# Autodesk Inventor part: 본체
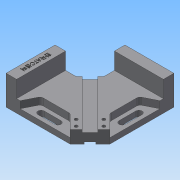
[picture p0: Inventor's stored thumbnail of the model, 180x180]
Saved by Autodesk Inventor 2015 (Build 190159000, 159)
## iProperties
Created: 2019-04
Part Number: 본체
Material: 알루미늄 6061
Document SubType Name: Modeling
Designer: user
Density: 2.7 g/cm^3
Appearance: 기본값
Author: user
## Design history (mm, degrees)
sketch "스케치1"
  geometry: L1 (60, 60)-(-60, 60); L2 (-60, 60)-(-60, -60); L3 (-60, -60)-(60, -60); L4 (60, -60)-(60, 60); L5 (60, 60)-(-60, -60); L6 (-60, 60)-(60, -60); 1 further point
  constraints: 12 end point, 2 midpoint, 2 parallel, 1 horizontal, 1 perpendicular
  dimensions: "d0" = 120 distance of L2.end L3.end; "d1" = 120 distance of L1.end L2.end
extrude "돌출1" new body sketch "스케치1" distance "d2" = 42; taper "d3" = 0 deg
sketch "스케치2"
  geometry: L1 (60, 60)-(-60, 60) reference; L2 (-60, 60)-(-60, -60) reference; L3 (60, -60)-(-45, -60); L4 (-45, -60)-(-45, 45); L5 (-45, 45)-(60, 45); L6 (60, 45)-(60, -60); 1 further point
  constraints: 8 end point, 2 parallel, 1 horizontal, 1 perpendicular
  dimensions: "d4" = 15 distance between parallel lines of L2 L4; "d5" = 15 distance between parallel lines of L1 L5
extrude "돌출2" cut sketch "스케치2" distance "d6" = 24; taper "d7" = 0 deg
sketch "스케치4"
  geometry: L1 (60, 45)-(60, -60) reference; L2 (60, -60)-(-45, -60) reference; L3 (60, -60)-(31.716, -60); L4 (60, -31.716)-(60, -60); L5 (31.716, -60)-(60, -31.716); 1 further point
  constraints: 6 end point, 2 point on line, 1 collinear
  dimensions: "d13" = 20 distance from line of L5 L1.end; "d14" = 45 deg angle of L1 L5
extrude "돌출3" cut sketch "스케치4" stored distance "d15" = 24; taper "d16" = 0 deg
sketch "스케치5"
  geometry: L1 (-60, 60)-(-10, 60); L2 (-10, 60)-(-10, 29.806); L3 (-29.806, 10)-(-60, 10); L4 (-60, 10)-(-60, 60); L5 (-29.806, 10)-(-10, 29.806); L6 (31.716, -60)-(60, -31.716) reference; 1 further point
  constraints: 10 end point, 3 parallel, 1 horizontal, 1 perpendicular
  dimensions: "d17" = 50 distance of L1.start L3.end; "d18" = 50 distance of L1.end L1.start; "d40" = 93 distance between parallel lines of L6 L5
extrude "돌출4" cut sketch "스케치5" stored distance "d21" = 24; taper "d22" = 0 deg
sketch "스케치6"
  geometry: L1 (31.716, -60)-(-45, -60) reference; L2 (31.716, -60)-(60, -31.716) reference; L3 (-40, -60)-(-30, -40); L4 (-30, -40)-(11.716, -40); L5 (11.716, -40)-(31.716, -60); L6 (-40, -60)-(31.716, -60); L7 (-60, 10)-(-60, -60) reference; L8 (60, 60)-(-10, 60) reference; 1 further point
  constraints: 8 end point, 1 collinear, 1 horizontal, 1 point on line
  dimensions: "d23" = 90 deg angle of L2 L5; "d24" = 20 distance between parallel lines of L1 L4; "d25" = 30 distance from line of L7 L3.end; "d26" = 20 distance from line of L7 L3.start
extrude "돌출5" cut sketch "스케치6" distance "d31" = 10; taper "d32" = 0 deg
sketch "스케치7"
  geometry: L1 (-30, -40)-(11.716, -40) reference; L2 (-20, -50)-(4, -50); L3 (-20, -54.5)-(4, -54.5); L4 (4, -45.5)-(-20, -45.5); L5 (-60, -60)-(-45, -60) reference; L6 (-60, 10)-(-60, -60) reference; A1 r 4.5 centre (-20, -50) between (-20, -45.5) and (-20, -54.5); A2 r 4.5 centre (4, -50) between (4, -54.5) and (4, -45.5); 2 further points
  constraints: 8 end point, 4 point on circle, 4 tangent, 2 centre point, 2 parallel, 1 midpoint
  dimensions: "d33" = 4.5 radius of A1; "d34" = 24 distance of L2.end L2.start; "d35" = 10 distance from line of L5 L2.start; "d36" = 40 distance from line of L6 L2.start
extrude "돌출6" cut sketch "스케치7" stored distance "d37" = 10; taper "d38" = 0 deg
node "작업 평면1"
sketch "스케치9"
  geometry: L1 (-10, 29.806)-(-29.806, 10) reference; L2 (31.716, -60)-(60, -31.716) reference; L3 (40.201, -51.515)-(-25.56, 14.246); L4 (-14.246, 25.56)-(51.515, -40.201); L5 (40.201, -51.515)-(51.515, -40.201); L6 (-25.56, 14.246)-(-14.246, 25.56); L7 (-19.903, 19.903)-(45.858, -45.858); 1 further point
  constraints: 10 end point, 4 point on line, 3 perpendicular, 2 collinear, 2 midpoint, 1 other
  dimensions: "d41" = 16 distance between parallel lines of L4 L3
extrude "돌출7" cut sketch "스케치9" distance "d42" = 3.5; taper "d43" = 0 deg
sketch "스케치10"
  geometry: L1 (-29.806, -10)-(-10, -29.806) reference; L2 (60, 31.716)-(31.716, 60) reference; L3 (50.101, 41.615)-(-15.66, -24.146); L4 (-24.146, -15.66)-(41.615, 50.101); L5 (50.101, 41.615)-(41.615, 50.101); L6 (-15.66, -24.146)-(-24.146, -15.66); L7 (-19.903, -19.903)-(45.858, 45.858); 1 further point
  constraints: 10 end point, 4 point on line, 3 perpendicular, 2 collinear, 2 midpoint, 1 other
  dimensions: "d45" = 12 distance of L3.start L4.end
extrude "돌출8" cut sketch "스케치10" distance "d46" = 3; taper "d47" = 0 deg
hole "구멍1" diameter "d50" = 4.5; stored, may be unused: countersink angle "d54" = 90 deg, drill point angle "d56" = 118 deg; dims "d48" = 6, "d51" = 6, "d52" = 8, "d53" = 10, "d55" = 8, "d58" = 6
sketch "스케치12"
  geometry: L1 (-45, 10)-(-60, 10) reference; L2 (-45, -60)-(-45, 10) reference; 2 further points
  constraints: 1 other
  dimensions: "d61" = 35 distance from line of L1 point (-52.5, -25); "d62" = 7.5 distance from line of L2 point (-52.5, -25)
feature "엠보싱1" sketch "스케치12" dims "d0" = 120, "d1" = 120, "d63" = 0.5, "d64" = 0
fillet "모깎기1" dims "d65" = 5
node "솔리드1"
mirror "대칭1"
pattern_linear "직사각형 패턴1" dims "d60" = 12
mirror "대칭2"
